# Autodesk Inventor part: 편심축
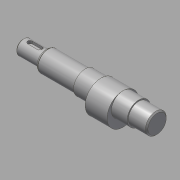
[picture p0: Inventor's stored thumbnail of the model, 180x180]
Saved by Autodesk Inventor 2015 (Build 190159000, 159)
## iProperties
Created: 2017-08
Part Number: 편심축
Material: 강철, 연강
Document SubType Name: Modeling
Designer: mduedu
Density: 1 g/cm^3
Appearance: 강철
Author: mduedu
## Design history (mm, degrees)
sketch "스케치1"
  geometry: L1 (0, 0)-(110, 0); L2 (110, 0)-(110, 8.5); L3 (110, 8.5)-(95, 8.5); L4 (95, 8.5)-(95, 9.5); L5 (95, 9.5)-(51, 9.5); L6 (51, 9.5)-(51, 8.5); L7 (51, 8.5)-(19, 8.5); L8 (19, 8.5)-(19, 6); L9 (19, 6)-(0, 6); L10 (0, 6)-(0, 0)
  constraints: 20 end point, 6 parallel, 2 collinear, 2 perpendicular, 1 horizontal
  dimensions: "d0" = 110 distance of L1.start L1.end; "d1" = 17 diameter of L3 L1; "d2" = 19 diameter of L5 L1; "d3" = 12 diameter of L9 L1; "d4" = 19 distance of L8.end L9.end; "d5" = 15 distance of L2.end L3.end; "d6" = 44 distance of L4.end L5.end
revolve "회전1" sketch "스케치1" stored, may be unused: angle "d7" = 90 deg
node "작업 평면1"
sketch "스케치2"
  geometry: C1 r 9.5 at (0, 0) reference; C2 r 13 at (0, -3.5); 1 further point
  constraints: 1 centre point, 1 tangent, 1 vertical alignment
  dimensions: "d8" = 3.5 distance of point (0, 0) C2.centre
extrude "돌출1" join sketch "스케치2" stored distance "d9" = 18; taper "d10" = 0 deg
chamfer "모따기1" distance "d11" = 1; stored, may be unused: second distance "d12" = 2, angle "d13" = 45 deg
node "작업 평면2"
sketch "스케치3"
  geometry: L1 (3.5, -2)-(-4.5, -2); L2 (-4.5, -2)-(-4.5, 2); L3 (-4.5, 2)-(3.5, 2); L4 (3.5, 2)-(3.5, -2); L5 (9.5, 6)-(9.5, -6) reference; A1 r 2 centre (3.5, 0) between (3.5, -2) and (3.5, 2); A2 r 2 centre (-4.5, 0) between (-4.5, 2) and (-4.5, -2); A3 r 2 centre (3.5, 0) between (3.5, 2) and (3.5, -2); A4 r 2 centre (-4.5, 0) between (-4.5, -2) and (-4.5, 2); 1 further point
  constraints: 8 end point, 8 point on circle, 4 centre point, 2 midpoint, 2 parallel, 1 horizontal, 1 horizontal alignment, 1 perpendicular
  dimensions: "d14" = 12 dimension on A2 A1; "d16" = 4 distance between parallel lines of L3 L1; "d17" = 4 distance edge to line of A1 L5
extrude "돌출2" cut sketch "스케치3" distance "d18" = 2.5; taper "d19" = 0 deg
chamfer "모따기2" distance "d20" = 1; stored, may be unused: second distance "d21" = 2, angle "d22" = 45 deg
chamfer "모따기3" distance "d23" = 1; stored, may be unused: second distance "d24" = 2, angle "d25" = 60 deg
fillet "모깎기1" dims "d26" = 0.5
hole "구멍1" diameter "d29" = 3.242; stored, may be unused: countersink angle "d33" = 90 deg, drill point angle "d35" = 118 deg; dims "d30" = 8, "d31" = 4, "d32" = 2, "d34" = 10, "d36" = 10, "d37" = 10
node "솔리드1"
node "절단 모서리 투영1"
